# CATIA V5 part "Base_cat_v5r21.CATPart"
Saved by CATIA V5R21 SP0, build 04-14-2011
Part number: Base
Bounding box of the stored display mesh (mm): x -24 to 24, y 0 to 90, z 0 to 54
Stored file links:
  D:\CATIA V5R21 E-RESOURCES\CATIA-V5R21\catia-v5r21-Tut\c14-catia-v5r21-tut\c14-catia-v5r21-tut02\Part & Asm files\Base_cat_v5r21.CATPart
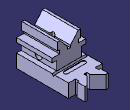
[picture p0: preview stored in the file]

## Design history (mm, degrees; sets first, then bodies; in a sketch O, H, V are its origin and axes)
Body1 (main body)
  Sketch1 on xy-plane, origin (0, 0, 0), H (1, 0, 0), V (0, 1, 0)
    line L1 (-24, 0) -> (24, 0)
    point P2 (24, 0)
    construction line L2 (-23.876, 50.8) -> (23.876, 50.8)
    point P3 (-23.876, 50.8)
    point P4 (23.876, 50.8)
    line L3 (24, 0) -> (24, 74)
    point P5 (24, 74)
    line L4 (24, 74) -> (14, 74)
    point P6 (14, 74)
    line L5 (14, 74) -> (14, 79)
    point P7 (14, 79)
    line L6 (14, 79) -> (16.5, 79)
    point P8 (16.5, 79)
    line L7 (16.5, 79) -> (16.5, 90)
    point P9 (16.5, 90)
    line L8 (16.5, 90) -> (13.5, 90)
    point P10 (13.5, 90)
    line L9 (13.5, 90) -> (2, 78.5)
    point P11 (2, 78.5)
    line L10 (2, 78.5) -> (2, 74)
    point P12 (2, 74)
    line L11 (2, 74) -> (0, 74)
    point P13 (0, 74)
    point P14 (0, 74)
    point P15 (-2, 74)
    line L12 (-2, 74) -> (0, 74)
    point P16 (-2, 78.5)
    line L13 (-2, 78.5) -> (-2, 74)
    point P17 (-13.5, 90)
    line L14 (-13.5, 90) -> (-2, 78.5)
    point P18 (-16.5, 90)
    line L15 (-16.5, 90) -> (-13.5, 90)
    point P19 (-16.5, 79)
    line L16 (-16.5, 79) -> (-16.5, 90)
    point P20 (-14, 79)
    line L17 (-14, 79) -> (-16.5, 79)
    point P21 (-14, 74)
    line L18 (-14, 74) -> (-14, 79)
    point P22 (-24, 74)
    line L19 (-24, 74) -> (-14, 74)
    point P23 (-23.876, 50.8)
    point P24 (23.876, 50.8)
    construction line L20 (23.876, 50.8) -> (-23.876, 50.8)
    point P25 (-24, 0)
    line L21 (-24, 0) -> (-24, 74)
    length L1 = 48
    distance P2 V = 24
    distance L13 L10 = 4
    distance L16 L7 = 33
    distance L5 L3 = 10
    length L18 = 5
    angle L14 L9 = 90
    distance L4 L8 = 16
    distance P17 P10 = 27
    distance L1 L8 = 90
    horizontal: L1 H, L2 H, L4 H, L6 H, L8 H, L11 H
    coincidence: H L1, P13 V, P13 P14, L12 L4
    vertical: L3 V, L5 V, L7 V, L10 V
    symmetry: P13 P14 V, P12 P15 V, L11 L12 V, P11 P16 V, L10 L13 V, P10 P17 V, L9 L14 V, P9 P18 V, L8 L15 V, P8 P19 V, L7 L16 V, P7 P20 V, L6 L17 V, P6 P21 V, L5 L18 V, P5 P22 V, L4 L19 V, P4 P23 V, P3 P24 V, L2 L20 V, P2 P25 V, L3 L21 V
  Pad1: profile Sketch1, direction (0, 0, 1), length 19
  Sketch2 on face of Pad1, origin (0, 0, 0), H (1, 0, 0), V (0, 0, 1)
    line L1 (17.5, 19) -> (17.5, 32)
    point P1 (17.5, 19)
    point P2 (17.5, 32)
    line L2 (17.5, 32) -> (24, 32)
    point P3 (24, 32)
    line L3 (24, 32) -> (24, 38)
    point P4 (24, 38)
    line L4 (24, 38) -> (13.5, 38)
    point P5 (13.5, 38)
    line L5 (13.5, 38) -> (13.5, 43)
    point P6 (13.5, 43)
    line L6 (13.5, 43) -> (16.5, 43)
    point P7 (16.5, 43)
    line L7 (16.5, 43) -> (16.5, 54)
    point P8 (16.5, 54)
    reference projected line E1 (24, 19) -> (-24, 19) from edge of Pad1
    reference projected line E2 (24, 0) -> (24, 19) from edge of Pad1
    line L8 (16.5, 54) -> (12.9083, 54)
    point P9 (12.9083, 54)
    point P10 (2, 41)
    line L9 (2, 41) -> (2, 38)
    point P11 (2, 38)
    line L10 (2, 38) -> (0, 38)
    point P12 (0, 38)
    line L11 (2, 41) -> (12.9083, 54)
    point P13 (-12.9083, 54)
    point P14 (-2, 41)
    line L12 (-2, 41) -> (-12.9083, 54)
    point P15 (0, 38)
    point P16 (-2, 38)
    line L13 (-2, 38) -> (0, 38)
    line L14 (-2, 41) -> (-2, 38)
    point P17 (-16.5, 54)
    line L15 (-16.5, 54) -> (-12.9083, 54)
    point P18 (-16.5, 43)
    line L16 (-16.5, 43) -> (-16.5, 54)
    point P19 (-13.5, 43)
    line L17 (-13.5, 43) -> (-16.5, 43)
    point P20 (-13.5, 38)
    line L18 (-13.5, 38) -> (-13.5, 43)
    point P21 (-24, 38)
    line L19 (-24, 38) -> (-13.5, 38)
    point P22 (-24, 32)
    line L20 (-24, 32) -> (-24, 38)
    point P23 (-17.5, 32)
    line L21 (-17.5, 32) -> (-24, 32)
    point P24 (-17.5, 19)
    line L22 (-17.5, 19) -> (-17.5, 32)
    line L23 (-17.5, 19) -> (17.5, 19)
    distance L2 H = 32
    distance L4 H = 38
    distance L6 H = 43
    distance L8 H = 54
    distance L9 V = 2
    length L9 = 3
    distance L22 L1 = 35
    distance L7 L16 = 33
    angle L12 L11 = 80
    distance L18 L5 = 27
    vertical: L1 V, L3 V, L5 V, L7 V, L9 V
    horizontal: L2 H, L4 H, L6 H, L8 H, L10 H, L23 H
    coincidence: P1 E1, L3 E2, P11 L4, P12 V, P12 P15
    symmetry: P9 P13 V, P10 P14 V, L11 L12 V, P12 P15 V, P11 P16 V, L10 L13 V, L9 L14 V, P8 P17 V, L8 L15 V, P7 P18 V, L7 L16 V, P6 P19 V, L6 L17 V, P5 P20 V, L5 L18 V, P4 P21 V, L4 L19 V, P3 P22 V, L3 L20 V, P2 P23 V, L2 L21 V, P1 P24 V, L1 L22 V
  Pad2: profile Sketch2, direction (0, 1, 0), length 50.8
  Sketch3 on face of Pad1, origin (4.0235, 27.8102, 0), H (1, 0, 0), V (0, -1, 0)
    point P1 (-4.0235, 2.8102)
    reference intersected line E1 through (-4.0235, 0) direction (0, 1) from yz-plane
    reference projected line E2 (-6.0235, 27.8102) -> (-16.9318, 27.8102) from edge [face of Pad2 from Sketch2.L12 | start face of Pad2]
    distance P1 E2 = 25
    coincidence: E1 P1
  Hole1: placed by Sketch3, at (0, 25, 0) direction (0, 0, 1), diameter 8, depth 54.102
  Sketch4 on face of Pad2, origin (17.5, 12.3932, 23.5222), H (0, 1, 0), V (0, 0, 1)
    point P1 (12.6068, 1.4778)
    reference projected line E1 (-12.3932, 8.4778) -> (-12.3932, -4.5222) from edge of Pad2
    reference projected line E2 (-12.3932, -23.5222) -> (61.6068, -23.5222) from edge of Pad1
    distance E1 P1 = 25
    distance E2 P1 = 25
  Hole2: placed by Sketch4, at (17.5, 25, 25) direction (-1, 0, 0), diameter 10, depth 54.102
  Sketch5 on face of Pad1, origin (0, 0, 19), H (1, 0, 0), V (0, 1, 0)
    construction line L1 (-24, 59) -> (24, 59)
    point P1 (-24, 59)
    point P2 (24, 59)
    construction line L2 (-12.5, 59) -> (12.5, 59)
    point P3 (-12.5, 59)
    point P4 (12.5, 59)
    line L3 (-12.5, 62) -> (12.5, 62)
    line L4 (12.5, 56) -> (-12.5, 56)
    arc A1 centre (12.5, 59) radius 3 from (12.5, 62) to (12.5, 56) cw
    arc A2 centre (-12.5, 59) radius 3 from (-12.5, 56) to (-12.5, 62) cw
    reference projected line E1 (24, 74) -> (24, 0) from edge of Pad1
    reference projected line E2 (-24, 74) -> (-24, 0) from edge of Pad1
    reference projected line E3 (24, 74) -> (14, 74) from edge [face of Pad1 from Sketch1.L4 | end face of Pad1]
    radius A1 = 3
    distance L2 E3 = 15
    length L2 = 25
    distance V P4 = 12.5
    horizontal: L1 H, L2 H
    coincidence: P3 L1, P2 E1, P1 E2
    tangency: A1 L3, A2 L3, A1 L4, A2 L4
    parallelism: L2 L3
  Pocket1: profile Sketch5, direction (0, 0, -1), length 1
  Sketch6 on face of Pad1, origin (24, 0, 0), H (0, 1, 0), V (0, 0, 1)
    point P1 (50.8, 19)
    line L1 (50.8, 19) -> (52.5321, 16)
    point P2 (52.5321, 16)
    line L2 (52.5321, 16) -> (54.2641, 19)
    line L3 (54.2641, 19) -> (50.8, 19)
    reference projected line E1 (74, 19) -> (0, 19) from edge of Pad1
    construction line L4 (52.5321, 16) -> (52.5321, 29.45)
    reference projected line E2 (50.8, 19) -> (50.8, 32) from edge [end face of Pad2 | face of Pad2 from Sketch2.L1]
    angle L1 L2 = 60
    distance P2 L3 = 3
    angle L4 L2 = 30
    horizontal: L3 H
    coincidence: L3 E1, P1 E2
    vertical: L4 V
  Pocket2: profile Sketch6, direction (-1, 0, 0), through (limit type 6)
